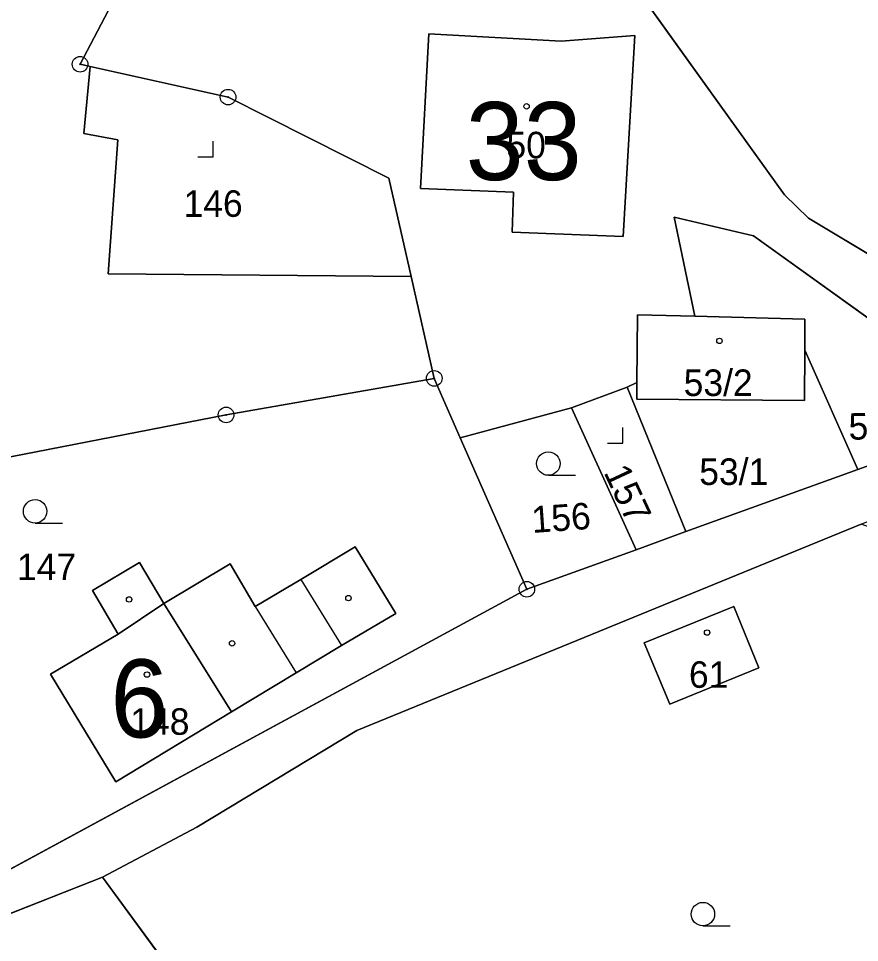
# Model space of a CAD drawing. Extents: x -689422 to -685210, y -987725 to -982160.
# Drawn here: x -686098.8 to -686044.9, y -987242.2 to -987183 of the extents above; entities that cross this region are included whole.
import ezdxf

# ---------------------------------------------------------------- set-up
doc = ezdxf.new("R2010")
doc.units = 0
for name, color, linetype in [('KN_Budovy', 7, 'Continuous'), ('KN_Budovy_cisla_domovni', 7, 'Continuous'), ('KN_Hranice_parcel', 7, 'Continuous'), ('KN_Hranice_parcel_vnitrni_kresba', 7, 'Continuous'), ('KN_Parcelni cisla', 7, 'Continuous'), ('KN_Polygon parcely', 7, 'Continuous'), ('KN_POZEMKY_OSTATNI PLOCHA', 7, 'Continuous'), ('KN_POZEMKY_ZAHRADA', 7, 'Continuous'), ('KN_POZEMKY_ZASTAVENA PLOCHA', 7, 'Continuous'), ('KN_VYUZITI_13_zastavena plocha_zboreniste', 7, 'Continuous'), ('KN_VYUZITI_17_ostatni plocha_ostatni komunikace', 7, 'Continuous'), ('KN_VYUZITI_26_ostatni plocha_jina plocha', 7, 'Continuous'), ('KN_Značky bodu BP', 7, 'Continuous'), ('KN_Značky budov', 7, 'Continuous'), ('KN_Značky kultur', 7, 'Continuous')]:
    doc.layers.add(name, color=color, linetype=linetype)

msp = doc.modelspace()

# ---------------------------------------------------------------- linework, layer by layer
at = {"layer": 'KN_Budovy'}
for points in [[(-686060.04, -987197), (-686059.89, -987194.44), (-686059.3, -987184.11), (-686064.02, -987184.48), (-686072.5, -987184.02), (-686073.03, -987193.93), (-686067.07, -987194.15), (-686067.16, -987196.72)], [(-686048.4, -987202.29), (-686055.46, -987202.1), (-686059.13, -987202.01), (-686059.17, -987206.36), (-686059.17, -987207.42), (-686048.42, -987207.5), (-686048.41, -987204.28)], [(-686096.75, -987225.04), (-686092.56, -987231.94), (-686085.15, -987227.46), (-686089.49, -987220.51), (-686092.41, -987222.48)], [(-686057.06, -987226.96), (-686051.35, -987224.64), (-686052.96, -987220.71), (-686058.69, -987223.03)]]:
    msp.add_lwpolyline(points, close=True, dxfattribs=at)
at = {"layer": 'KN_Hranice_parcel'}
for p, q in [((-686094.22, -987186.1), (-686094.86, -987185.96)), ((-686085.37, -987188.07), (-686094.22, -987186.1)), ((-686075.07, -987193.26), (-686085.37, -987188.07)), ((-686073.64, -987199.56), (-686075.07, -987193.26)), ((-686072.16, -987206.09), (-686073.64, -987199.56)), ((-686048.41, -987204.28), (-686045.01, -987211.93)), ((-686072.16, -987206.09), (-686070.49, -987209.9)), ((-686063.35, -987207.97), (-686059.79, -987206.65)), ((-686059.79, -987206.65), (-686059.17, -987206.36)), ((-686056.02, -987215.91), (-686059.79, -987206.65)), ((-686070.49, -987209.9), (-686063.35, -987207.97)), ((-686059.21, -987217.07), (-686063.35, -987207.97)), ((-686066.22, -987219.6), (-686070.49, -987209.9)), ((-686041.03, -987210.49), (-686045.01, -987211.93)), ((-686045.01, -987211.93), (-686056.02, -987215.91)), ((-686044.78, -987215.43), (-686077.11, -987228.66)), ((-686056.02, -987215.91), (-686059.21, -987217.07)), ((-686059.21, -987217.07), (-686066.22, -987219.6)), ((-686066.22, -987219.6), (-686103.42, -987239.75)), ((-686103.18, -987241.89), (-686093.43, -987238.06)), ((-686093.43, -987238.06), (-686072.79, -987266.16))]:
    msp.add_line(p, q, dxfattribs=at)
for points in [[(-686094.86, -987185.96), (-686089.52, -987175.76), (-686084.61, -987165.61)], [(-686062.52, -987176.48), (-686049.71, -987194.34), (-686048.16, -987195.83), (-686037.31, -987202.35)], [(-686060.04, -987197), (-686067.16, -987196.72), (-686067.07, -987194.15), (-686073.03, -987193.93), (-686072.5, -987184.02), (-686064.02, -987184.48), (-686059.3, -987184.11), (-686059.89, -987194.44), (-686060.04, -987197)], [(-686073.64, -987199.56), (-686093.07, -987199.39), (-686092.45, -987190.8), (-686094.62, -987190.4), (-686094.22, -987186.1)], [(-686055.46, -987202.1), (-686056.78, -987195.76), (-686051.69, -987196.96), (-686041.76, -987204.1), (-686034.23, -987207.05)], [(-686059.17, -987206.36), (-686059.13, -987202.01), (-686055.46, -987202.1)], [(-686055.46, -987202.1), (-686048.4, -987202.29), (-686048.41, -987204.28)], [(-686048.41, -987204.28), (-686048.42, -987207.5), (-686059.17, -987207.42), (-686059.17, -987206.36)], [(-686117.99, -987214.8), (-686100.11, -987211.26), (-686085.5, -987208.43), (-686072.16, -987206.09)], [(-686092.41, -987222.48), (-686094.06, -987219.69), (-686091.05, -987217.89), (-686089.49, -987220.51), (-686085.25, -987217.98), (-686083.63, -987220.7), (-686080.72, -987218.97), (-686077.22, -987216.88), (-686074.61, -987221.16), (-686078.1, -987223.21), (-686081, -987224.96), (-686085.15, -987227.46), (-686092.56, -987231.94), (-686096.75, -987225.04), (-686092.41, -987222.48)], [(-686057.06, -987226.96), (-686058.69, -987223.03), (-686052.96, -987220.71), (-686051.35, -987224.64), (-686057.06, -987226.96)], [(-686077.11, -987228.66), (-686087.38, -987234.85), (-686093.43, -987238.06)]]:
    msp.add_lwpolyline(points, dxfattribs=at)
at = {"layer": 'KN_Hranice_parcel_vnitrni_kresba'}
for p, q in [((-686080.72, -987218.97), (-686078.1, -987223.21)), ((-686092.41, -987222.48), (-686089.49, -987220.51)), ((-686089.49, -987220.51), (-686085.15, -987227.46)), ((-686083.63, -987220.7), (-686081, -987224.96))]:
    msp.add_line(p, q, dxfattribs=at)
at = {"layer": 'KN_Polygon parcely'}
for points in [[(-686022.69, -987186.83), (-686015.35, -987178.81), (-686013.64, -987175.93), (-686009.27, -987168.77), (-686024.17, -987155.85), (-686031.47, -987166.15), (-686036.92, -987174.81), (-686056.78, -987164.6), (-686062.52, -987176.48), (-686049.71, -987194.34), (-686048.16, -987195.83), (-686037.31, -987202.35)], [(-686100.11, -987211.26), (-686085.5, -987208.43), (-686072.16, -987206.09), (-686073.64, -987199.56), (-686093.07, -987199.39), (-686092.45, -987190.8), (-686094.62, -987190.4), (-686094.22, -987186.1), (-686094.86, -987185.96), (-686089.52, -987175.76), (-686084.61, -987165.61), (-686089.61, -987170.9), (-686096.63, -987177.58), (-686101.64, -987182.03), (-686111.39, -987199.29), (-686112.76, -987200.83), (-686117.92, -987212.85), (-686117.99, -987214.8)], [(-686060.04, -987197), (-686067.16, -987196.72), (-686067.07, -987194.15), (-686073.03, -987193.93), (-686072.5, -987184.02), (-686064.02, -987184.48), (-686059.3, -987184.11), (-686059.89, -987194.44)], [(-686060.04, -987197), (-686059.89, -987194.44), (-686059.3, -987184.11), (-686064.02, -987184.48), (-686072.5, -987184.02), (-686073.03, -987193.93), (-686067.07, -987194.15), (-686067.16, -987196.72)], [(-686085.37, -987188.07), (-686094.22, -987186.1), (-686094.62, -987190.4), (-686092.45, -987190.8), (-686093.07, -987199.39), (-686073.64, -987199.56), (-686075.07, -987193.26)], [(-686048.4, -987202.29), (-686048.41, -987204.28), (-686045.01, -987211.93), (-686041.03, -987210.49), (-686034.23, -987207.05), (-686041.76, -987204.1), (-686051.69, -987196.96), (-686056.78, -987195.76), (-686055.46, -987202.1)], [(-686055.46, -987202.1), (-686059.13, -987202.01), (-686059.17, -987206.36), (-686059.17, -987207.42), (-686048.42, -987207.5), (-686048.41, -987204.28), (-686048.4, -987202.29)], [(-686048.41, -987204.28), (-686048.42, -987207.5), (-686059.17, -987207.42), (-686059.17, -987206.36), (-686059.79, -987206.65), (-686056.02, -987215.91), (-686045.01, -987211.93)], [(-686109.32, -987229.36), (-686108.51, -987231.06), (-686103.42, -987239.75), (-686066.22, -987219.6), (-686070.49, -987209.9), (-686072.16, -987206.09), (-686085.5, -987208.43), (-686100.11, -987211.26), (-686117.99, -987214.8), (-686114.52, -987233.78)], [(-686056.02, -987215.91), (-686059.79, -987206.65), (-686063.35, -987207.97), (-686059.21, -987217.07)], [(-686059.21, -987217.07), (-686063.35, -987207.97), (-686070.49, -987209.9), (-686066.22, -987219.6)], [(-686127.57, -987258.87), (-686116.02, -987249.54), (-686103.18, -987241.89), (-686093.43, -987238.06), (-686087.38, -987234.85), (-686077.11, -987228.66), (-686044.78, -987215.43), (-686038.87, -987213.01), (-686041.03, -987210.49), (-686045.01, -987211.93), (-686056.02, -987215.91), (-686059.21, -987217.07), (-686066.22, -987219.6), (-686103.42, -987239.75), (-686126.27, -987252.79), (-686149.26, -987267.33), (-686167.7, -987279.33), (-686201.89, -987300.72), (-686206.95, -987311.19), (-686151.27, -987274.15)], [(-686023.87, -987226.5), (-686028.93, -987228.86), (-686031.57, -987230.28), (-686033.72, -987229.57), (-686034.99, -987226.59), (-686031.45, -987224.06), (-686033.92, -987220.3), (-686034.82, -987218.99), (-686044.78, -987215.43), (-686077.11, -987228.66), (-686087.38, -987234.85), (-686093.43, -987238.06), (-686072.79, -987266.16), (-686030.62, -987259.58), (-686020.8, -987258.73)], [(-686092.41, -987222.48), (-686094.06, -987219.69), (-686091.05, -987217.89), (-686089.49, -987220.51), (-686085.25, -987217.98), (-686083.63, -987220.7), (-686080.72, -987218.97), (-686077.22, -987216.88), (-686074.61, -987221.16), (-686078.1, -987223.21), (-686081, -987224.96), (-686085.15, -987227.46), (-686092.56, -987231.94), (-686096.75, -987225.04)], [(-686092.41, -987222.48), (-686096.75, -987225.04), (-686092.56, -987231.94), (-686085.15, -987227.46), (-686081, -987224.96), (-686078.1, -987223.21), (-686074.61, -987221.16), (-686077.22, -987216.88), (-686080.72, -987218.97), (-686083.63, -987220.7), (-686085.25, -987217.98), (-686089.49, -987220.51), (-686091.05, -987217.89), (-686094.06, -987219.69)], [(-686057.06, -987226.96), (-686058.69, -987223.03), (-686052.96, -987220.71), (-686051.35, -987224.64)], [(-686057.06, -987226.96), (-686051.35, -987224.64), (-686052.96, -987220.71), (-686058.69, -987223.03)], [(-686072.79, -987266.16), (-686093.43, -987238.06), (-686103.18, -987241.89), (-686108.02, -987246.74), (-686114.16, -987252.9), (-686107.75, -987265.29), (-686104.29, -987271.96)]]:
    msp.add_lwpolyline(points, close=True, dxfattribs=at)
msp.add_lwpolyline([(-686089.52, -987175.76), (-686094.86, -987185.96), (-686094.22, -987186.1), (-686085.37, -987188.07), (-686075.07, -987193.26), (-686073.64, -987199.56), (-686072.16, -987206.09), (-686070.49, -987209.9), (-686063.35, -987207.97), (-686059.79, -987206.65), (-686059.17, -987206.36), (-686059.13, -987202.01), (-686055.46, -987202.1), (-686056.78, -987195.76), (-686051.69, -987196.96), (-686041.76, -987204.1), (-686034.23, -987207.05), (-686029.33, -987204.58), (-686034.31, -987203.52), (-686037.31, -987202.35), (-686048.16, -987195.83), (-686049.71, -987194.34), (-686062.52, -987176.48)], dxfattribs=at)
at = {"layer": 'KN_POZEMKY_OSTATNI PLOCHA'}
for p, q in [((-686048.42, -987207.5), (-686048.41, -987204.28)), ((-686048.41, -987204.28), (-686045.01, -987211.93)), ((-686059.79, -987206.65), (-686059.17, -987206.36)), ((-686056.02, -987215.91), (-686059.79, -987206.65)), ((-686059.17, -987206.36), (-686059.17, -987207.42)), ((-686059.17, -987207.42), (-686048.42, -987207.5)), ((-686045.01, -987211.93), (-686041.03, -987210.49)), ((-686045.01, -987211.93), (-686056.02, -987215.91)), ((-686056.02, -987215.91), (-686045.01, -987211.93)), ((-686044.78, -987215.43), (-686077.11, -987228.66)), ((-686059.21, -987217.07), (-686056.02, -987215.91)), ((-686066.22, -987219.6), (-686059.21, -987217.07)), ((-686103.42, -987239.75), (-686066.22, -987219.6)), ((-686077.11, -987228.66), (-686087.38, -987234.85)), ((-686087.38, -987234.85), (-686093.43, -987238.06)), ((-686093.43, -987238.06), (-686103.18, -987241.89))]:
    msp.add_line(p, q, dxfattribs=at)
at = {"layer": 'KN_POZEMKY_ZAHRADA'}
for p, q in [((-686094.86, -987185.96), (-686089.52, -987175.76)), ((-686089.52, -987175.76), (-686094.86, -987185.96)), ((-686049.71, -987194.34), (-686062.52, -987176.48)), ((-686062.52, -987176.48), (-686049.71, -987194.34)), ((-686072.5, -987184.02), (-686073.03, -987193.93)), ((-686064.02, -987184.48), (-686072.5, -987184.02)), ((-686059.3, -987184.11), (-686064.02, -987184.48)), ((-686059.89, -987194.44), (-686059.3, -987184.11)), ((-686094.22, -987186.1), (-686094.86, -987185.96)), ((-686094.86, -987185.96), (-686094.22, -987186.1)), ((-686094.22, -987186.1), (-686094.62, -987190.4)), ((-686085.37, -987188.07), (-686094.22, -987186.1)), ((-686075.07, -987193.26), (-686085.37, -987188.07)), ((-686094.62, -987190.4), (-686092.45, -987190.8)), ((-686092.45, -987190.8), (-686093.07, -987199.39)), ((-686073.64, -987199.56), (-686075.07, -987193.26)), ((-686073.03, -987193.93), (-686067.07, -987194.15)), ((-686067.07, -987194.15), (-686067.16, -987196.72)), ((-686060.04, -987197), (-686059.89, -987194.44)), ((-686048.16, -987195.83), (-686049.71, -987194.34)), ((-686049.71, -987194.34), (-686048.16, -987195.83)), ((-686055.46, -987202.1), (-686056.78, -987195.76)), ((-686056.78, -987195.76), (-686051.69, -987196.96)), ((-686051.69, -987196.96), (-686056.78, -987195.76)), ((-686056.78, -987195.76), (-686055.46, -987202.1)), ((-686037.31, -987202.35), (-686048.16, -987195.83)), ((-686048.16, -987195.83), (-686037.31, -987202.35)), ((-686067.16, -987196.72), (-686060.04, -987197)), ((-686051.69, -987196.96), (-686041.76, -987204.1)), ((-686041.76, -987204.1), (-686051.69, -987196.96)), ((-686093.07, -987199.39), (-686073.64, -987199.56)), ((-686072.16, -987206.09), (-686073.64, -987199.56)), ((-686073.64, -987199.56), (-686072.16, -987206.09)), ((-686059.13, -987202.01), (-686059.17, -987206.36)), ((-686055.46, -987202.1), (-686059.13, -987202.01)), ((-686048.4, -987202.29), (-686055.46, -987202.1)), ((-686048.41, -987204.28), (-686048.4, -987202.29)), ((-686045.01, -987211.93), (-686048.41, -987204.28)), ((-686085.5, -987208.43), (-686072.16, -987206.09)), ((-686072.16, -987206.09), (-686085.5, -987208.43)), ((-686070.49, -987209.9), (-686072.16, -987206.09)), ((-686072.16, -987206.09), (-686070.49, -987209.9)), ((-686059.79, -987206.65), (-686063.35, -987207.97)), ((-686059.17, -987206.36), (-686059.79, -987206.65)), ((-686063.35, -987207.97), (-686070.49, -987209.9)), ((-686070.49, -987209.9), (-686063.35, -987207.97)), ((-686063.35, -987207.97), (-686059.21, -987217.07)), ((-686100.11, -987211.26), (-686085.5, -987208.43)), ((-686085.5, -987208.43), (-686100.11, -987211.26)), ((-686070.49, -987209.9), (-686066.22, -987219.6)), ((-686066.22, -987219.6), (-686070.49, -987209.9)), ((-686041.03, -987210.49), (-686045.01, -987211.93)), ((-686077.11, -987228.66), (-686044.78, -987215.43)), ((-686077.22, -987216.88), (-686080.72, -987218.97)), ((-686074.61, -987221.16), (-686077.22, -987216.88)), ((-686059.21, -987217.07), (-686066.22, -987219.6)), ((-686091.05, -987217.89), (-686094.06, -987219.69)), ((-686089.49, -987220.51), (-686091.05, -987217.89)), ((-686085.25, -987217.98), (-686089.49, -987220.51)), ((-686083.63, -987220.7), (-686085.25, -987217.98)), ((-686080.72, -987218.97), (-686083.63, -987220.7)), ((-686066.22, -987219.6), (-686103.42, -987239.75)), ((-686094.06, -987219.69), (-686092.41, -987222.48)), ((-686052.96, -987220.71), (-686058.69, -987223.03)), ((-686051.35, -987224.64), (-686052.96, -987220.71)), ((-686078.1, -987223.21), (-686074.61, -987221.16)), ((-686092.41, -987222.48), (-686096.75, -987225.04)), ((-686081, -987224.96), (-686078.1, -987223.21)), ((-686058.69, -987223.03), (-686057.06, -987226.96)), ((-686057.06, -987226.96), (-686051.35, -987224.64)), ((-686096.75, -987225.04), (-686092.56, -987231.94)), ((-686085.15, -987227.46), (-686081, -987224.96)), ((-686092.56, -987231.94), (-686085.15, -987227.46)), ((-686087.38, -987234.85), (-686077.11, -987228.66)), ((-686093.43, -987238.06), (-686087.38, -987234.85)), ((-686103.18, -987241.89), (-686093.43, -987238.06)), ((-686093.43, -987238.06), (-686072.79, -987266.16)), ((-686072.79, -987266.16), (-686093.43, -987238.06))]:
    msp.add_line(p, q, dxfattribs=at)
at = {"layer": 'KN_POZEMKY_ZASTAVENA PLOCHA'}
for p, q in [((-686073.03, -987193.93), (-686072.5, -987184.02)), ((-686072.5, -987184.02), (-686064.02, -987184.48)), ((-686064.02, -987184.48), (-686059.3, -987184.11)), ((-686059.3, -987184.11), (-686059.89, -987194.44)), ((-686094.62, -987190.4), (-686094.22, -987186.1)), ((-686094.22, -987186.1), (-686085.37, -987188.07)), ((-686085.37, -987188.07), (-686075.07, -987193.26)), ((-686092.45, -987190.8), (-686094.62, -987190.4)), ((-686093.07, -987199.39), (-686092.45, -987190.8)), ((-686075.07, -987193.26), (-686073.64, -987199.56)), ((-686067.07, -987194.15), (-686073.03, -987193.93)), ((-686067.16, -987196.72), (-686067.07, -987194.15)), ((-686059.89, -987194.44), (-686060.04, -987197)), ((-686060.04, -987197), (-686067.16, -987196.72)), ((-686073.64, -987199.56), (-686093.07, -987199.39)), ((-686059.17, -987206.36), (-686059.13, -987202.01)), ((-686059.13, -987202.01), (-686055.46, -987202.1)), ((-686055.46, -987202.1), (-686048.4, -987202.29)), ((-686048.4, -987202.29), (-686048.41, -987204.28)), ((-686048.41, -987204.28), (-686048.42, -987207.5)), ((-686063.35, -987207.97), (-686059.79, -987206.65)), ((-686059.79, -987206.65), (-686056.02, -987215.91)), ((-686059.17, -987207.42), (-686059.17, -987206.36)), ((-686048.42, -987207.5), (-686059.17, -987207.42)), ((-686059.21, -987217.07), (-686063.35, -987207.97)), ((-686056.02, -987215.91), (-686059.21, -987217.07)), ((-686080.72, -987218.97), (-686077.22, -987216.88)), ((-686077.22, -987216.88), (-686074.61, -987221.16)), ((-686094.06, -987219.69), (-686091.05, -987217.89)), ((-686091.05, -987217.89), (-686089.49, -987220.51)), ((-686089.49, -987220.51), (-686085.25, -987217.98)), ((-686085.25, -987217.98), (-686083.63, -987220.7)), ((-686083.63, -987220.7), (-686080.72, -987218.97)), ((-686092.41, -987222.48), (-686094.06, -987219.69)), ((-686058.69, -987223.03), (-686052.96, -987220.71)), ((-686052.96, -987220.71), (-686051.35, -987224.64)), ((-686074.61, -987221.16), (-686078.1, -987223.21)), ((-686096.75, -987225.04), (-686092.41, -987222.48)), ((-686078.1, -987223.21), (-686081, -987224.96)), ((-686057.06, -987226.96), (-686058.69, -987223.03)), ((-686051.35, -987224.64), (-686057.06, -987226.96)), ((-686092.56, -987231.94), (-686096.75, -987225.04)), ((-686081, -987224.96), (-686085.15, -987227.46)), ((-686085.15, -987227.46), (-686092.56, -987231.94))]:
    msp.add_line(p, q, dxfattribs=at)
at = {"layer": 'KN_VYUZITI_13_zastavena plocha_zboreniste'}
for p, q in [((-686094.62, -987190.4), (-686094.22, -987186.1)), ((-686094.22, -987186.1), (-686085.37, -987188.07)), ((-686085.37, -987188.07), (-686075.07, -987193.26)), ((-686092.45, -987190.8), (-686094.62, -987190.4)), ((-686093.07, -987199.39), (-686092.45, -987190.8)), ((-686075.07, -987193.26), (-686073.64, -987199.56)), ((-686073.64, -987199.56), (-686093.07, -987199.39)), ((-686063.35, -987207.97), (-686059.79, -987206.65)), ((-686059.79, -987206.65), (-686056.02, -987215.91)), ((-686059.21, -987217.07), (-686063.35, -987207.97)), ((-686056.02, -987215.91), (-686059.21, -987217.07))]:
    msp.add_line(p, q, dxfattribs=at)
at = {"layer": 'KN_VYUZITI_17_ostatni plocha_ostatni komunikace'}
for p, q in [((-686045.01, -987211.93), (-686041.03, -987210.49)), ((-686056.02, -987215.91), (-686045.01, -987211.93)), ((-686044.78, -987215.43), (-686077.11, -987228.66)), ((-686059.21, -987217.07), (-686056.02, -987215.91)), ((-686066.22, -987219.6), (-686059.21, -987217.07)), ((-686103.42, -987239.75), (-686066.22, -987219.6)), ((-686077.11, -987228.66), (-686087.38, -987234.85)), ((-686087.38, -987234.85), (-686093.43, -987238.06)), ((-686093.43, -987238.06), (-686103.18, -987241.89))]:
    msp.add_line(p, q, dxfattribs=at)
at = {"layer": 'KN_VYUZITI_26_ostatni plocha_jina plocha'}
for p, q in [((-686048.42, -987207.5), (-686048.41, -987204.28)), ((-686048.41, -987204.28), (-686045.01, -987211.93)), ((-686059.79, -987206.65), (-686059.17, -987206.36)), ((-686056.02, -987215.91), (-686059.79, -987206.65)), ((-686059.17, -987206.36), (-686059.17, -987207.42)), ((-686059.17, -987207.42), (-686048.42, -987207.5)), ((-686045.01, -987211.93), (-686056.02, -987215.91))]:
    msp.add_line(p, q, dxfattribs=at)
at = {"layer": 'KN_Značky bodu BP'}
for centre, radius in [((-686094.86, -987185.96), 0.5), ((-686094.86, -987185.96), 0.0303), ((-686085.37, -987188.07), 0.5), ((-686085.37, -987188.07), 0.0303), ((-686072.16, -987206.09), 0.5), ((-686072.16, -987206.09), 0.0303), ((-686085.5, -987208.43), 0.5), ((-686085.5, -987208.43), 0.0303), ((-686066.22, -987219.6), 0.5), ((-686066.22, -987219.6), 0.0303)]:
    msp.add_circle(centre, radius, dxfattribs=at)
at = {"layer": 'KN_Značky budov'}
for centre in [(-686066.237, -987188.659), (-686053.877, -987203.689), (-686091.717, -987220.259), (-686077.657, -987220.169), (-686054.667, -987222.379), (-686085.117, -987223.069), (-686090.567, -987225.069)]:
    msp.add_circle(centre, 0.175, dxfattribs=at)
at = {"layer": 'KN_Značky kultur'}
for p, q in [((-686086.32, -987191.9), (-686086.32, -987190.9)), ((-686087.321, -987191.9), (-686086.32, -987191.9)), ((-686060.06, -987210.24), (-686060.06, -987209.24)), ((-686061.061, -987210.24), (-686060.06, -987210.24)), ((-686064.843, -987212.3), (-686063.093, -987212.3)), ((-686097.743, -987215.36), (-686095.993, -987215.36)), ((-686054.933, -987241.17), (-686053.183, -987241.17))]:
    msp.add_line(p, q, dxfattribs=at)
for centre in [(-686064.843, -987211.55), (-686097.743, -987214.61), (-686054.933, -987240.42)]:
    msp.add_circle(centre, 0.75, dxfattribs=at)

# ---------------------------------------------------------------- texts
at = {"layer": 'KN_Budovy_cisla_domovni'}
for s, p in [('33', (-686070.14, -987193.384)), ('6', (-686092.918, -987229.099))]:
    msp.add_text(s, height=5, dxfattribs=at).set_placement(p)
at = {"layer": 'KN_Parcelni cisla'}
for s, p in [('50', (-686067.53, -987191.99)), ('146', (-686088.23, -987195.74)), ('53/2', (-686056.169, -987207.22)), ('53/1', (-686055.169, -987212.92)), ('147', (-686098.91, -987219.02)), ('61', (-686055.83, -987225.92)), ('148', (-686091.64, -987228.93))]:
    msp.add_text(s, height=1.7, dxfattribs=at).set_placement(p)
for s, rotation, p in [('54/1', 1, (-686045.584, -987210.026)), ('157', 295, (-686061.32, -987212.109)), ('156', 4, (-686065.86, -987215.997))]:
    msp.add_text(s, height=1.7, rotation=rotation, dxfattribs=at).set_placement(p)

doc.saveas('drawing.dxf')
